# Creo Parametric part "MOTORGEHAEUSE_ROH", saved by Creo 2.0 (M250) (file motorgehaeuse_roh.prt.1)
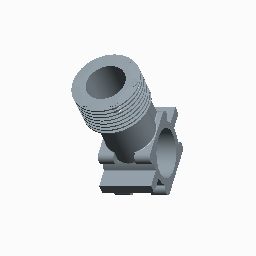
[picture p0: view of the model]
Units: millimeter Kilogram Sec (mmKs); MM, KILOGRAM, SECS
Materials in the file: STAHL

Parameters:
  PTC_MATERIAL_NAME = "STAHL"
  WERKSTOFF = "Stahl"
  ERSTELLER = "ARINDA"
  BENENNUNG = "XXX"
  TEILETYP = "K"

Other parameters: MASSE

Created from: ARINDA_STARTTEIL.PRT

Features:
  1. coordinate system
  2. datum plane "RECHTS_Y-Z"
  3. datum plane "OBEN_X-Z"
  4. datum plane "VORNE_X-Y"
  5. datum axis
  6. datum axis
  7. datum axis
  8. datum point "PNT0"
  9. extrusion "Profil 1", "Schnitt 1"
  10. extrusion "Profil 2", "Schnitt 1"
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
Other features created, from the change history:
  coordinate system "CS1"
  extrusion "Profil 3"
  extrusion "Profil 4"
  extrusion "Profil 5"
  mirror "Spiegeln 1"
  extrusion "Profil 5 (2)"
  hole "Bohrung 1"
  hole "Bohrung 2"
  extruded cut "Profil 6"
  round "Rundung 1"
  round "Rundung 2"
  extrusion "Profil 7"
  pattern "Muster 1"
  extrusion "Profil 7 [2]"
  extrusion "Profil 7 [3]"
  extrusion "Profil 7 [4]"
  extrusion "Profil 7 [5]"
  extrusion "Profil 7 [6]"
  revolve "Drehen 1"
  pattern "Muster 2"
  revolve "Drehen 1 [2]"
  revolve "Drehen 1 [3]"
  revolve "Drehen 1 [4]"
  revolve "Drehen 1 [5]"
  revolve "Drehen 1 [6]"
  revolve "Drehen 1 [7]"
  revolve "Drehen 1 [8]"
  group "LOCAL_GROUP"
  round "Rundung 3"
  round "Rundung 4"
  round "Rundung 5"
  round "Rundung 6"
  round "Rundung 7"
  round "Rundung 8"
  round "Rundung 9"
  round "Rundung 10"
  round "Rundung 11"
  round "Rundung 12"

Other named items: A_X, A_Y, A_Z, CS0

Layers: 01_ACHSEN, 01_ACHSEN_STD, 01_EBENEN_STD, 01_KOORDSYS_STD, 01_PUNKTE_STD, VOLUMENGEOMETRIE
